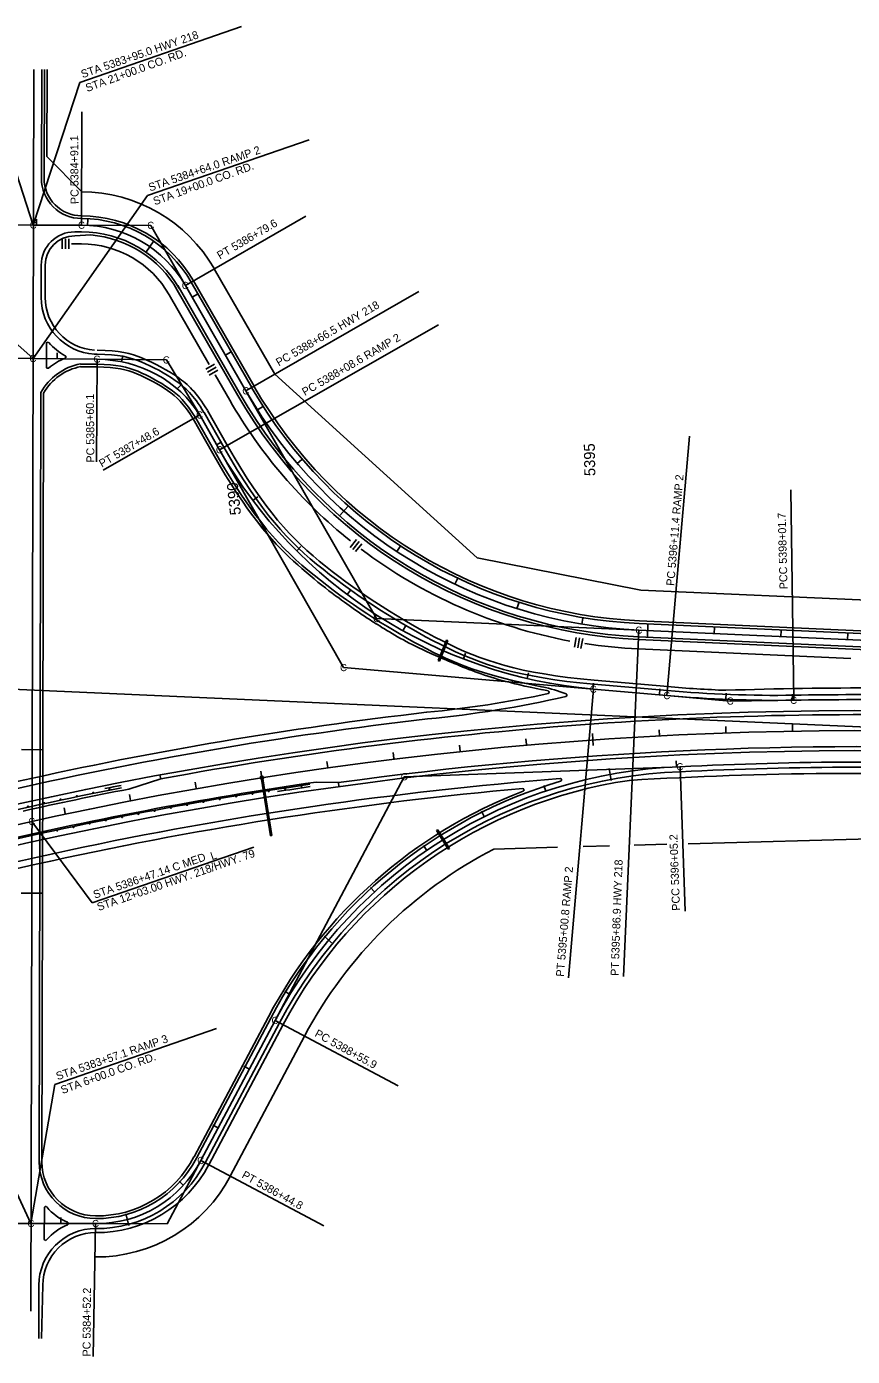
# Model space of a CAD drawing. Extents: x 192699 to 285914, y 194342 to 233219.
# Drawn here: x 282526 to 283763, y 220073 to 222066 of the extents above; entities that cross this region are included whole.
import ezdxf

# ---------------------------------------------------------------- set-up
doc = ezdxf.new("R2010")
doc.units = 0
for name, color, linetype in [('CENT LINE', 7, 'Continuous'), ('CONCRETE', 7, 'Continuous'), ('CURVE DATA', 7, 'Continuous'), ('CURVE LINE', 7, 'Continuous'), ('DRAINAGE', 7, 'Continuous'), ('GUARD RAILS', 7, 'Continuous'), ('R-W - CofA', 7, 'Continuous'), ('ROAD', 7, 'Continuous'), ('SHOULDER', 7, 'Continuous'), ('STATIONING1', 7, 'Continuous'), ('TEXT', 7, 'Continuous')]:
    doc.layers.add(name, color=color, linetype=linetype)

msp = doc.modelspace()

# ---------------------------------------------------------------- linework, layer by layer
at = {"layer": 'CENT LINE'}
for p, q in [((282531.8, 220140.9), (282536.2, 222002.1)), ((282442.4, 221769), (282535.6, 221768.8)), ((282535.6, 221768.8), (282607.9, 221768.6)), ((282763.6, 221678.2), (282854.2, 221520.3)), ((282453.4, 221569.7), (282631.3, 221567.7)), ((282785, 221484.1), (282814.7, 221432)), ((283443.5, 221161.5), (284035.7, 221135.1)), ((283375.2, 221073), (283485.4, 221063.5)), ((282898, 220576.6), (282786.7, 220366.6)), ((282404.9, 220272.5), (282532.1, 220272.2)), ((282532.1, 220272.2), (282629, 220272))]:
    msp.add_line(p, q, dxfattribs=at)
for centre, radius, start, end in [((282607.5, 221588.6), 180, 29.8667, 89.8681), ((283475.3, 221877), 716.2, 209.8667, 267.45), ((283650.1, 222966.2), 1909.9, 265.0516, 270.7606), ((283775, 215280.8), 5776.6, 87.38243, 90.99192), ((283775, 215280.8), 5730.1, 87.45001, 121.03334), ((283530.8, 220241), 716.2, 92.0659, 152.0654), ((283788.1, 215280.9), 5683, 87.5824, 92.8561), ((282630.7, 220447.8), 175.8, 269.4227, 332.4898)]:
    msp.add_arc(centre, radius, start, end, dxfattribs=at)
for centre, major_axis, ratio, start_param, end_param in [((282629.3, 221403.5), (178.6, 0), 0.919139, 0.512787, 1.560009), ((283440.8, 221780.5), (-718.5, 0), 0.988738, 0.51279, 1.479284)]:
    msp.add_ellipse(centre, major_axis=major_axis, ratio=ratio, start_param=start_param, end_param=end_param, dxfattribs=at)
at = {"layer": 'CONCRETE'}
for p, q in [((282726.5, 220938.6), (282725.4, 220944.5)), ((282726.5, 220938.6), (282678.6, 220923.4)), ((282993, 220933.1), (282959.8, 220933.9)), ((282993.8, 220927.1), (282993, 220933.1))]:
    msp.add_line(p, q, dxfattribs=at)
for radius, start, end in [(5711.6, 98.2059, 103.4241), (5748.1, 100.99633, 102.60615)]:
    msp.add_arc((283775, 215280.8), radius, start, end, dxfattribs=at)
at = {"layer": 'CURVE LINE'}
for p, q in [((282607.9, 221768.6), (282711.8, 221768.3)), ((282711.8, 221768.3), (282763.6, 221678.2)), ((282631.3, 221567.7), (282735.1, 221566.6)), ((282735.1, 221566.6), (282785, 221484.1)), ((282854.2, 221520.3), (283050.2, 221179)), ((282814.7, 221432), (283000.8, 221105.5)), ((283050.2, 221179), (283443.5, 221161.5)), ((283000.8, 221105.5), (283375.2, 221073)), ((282302.5, 221082.2), (284029.9, 221005.2)), ((283485.4, 221063.5), (283580.2, 221055.3)), ((283580.2, 221055.3), (283675.4, 221056.6)), ((283491, 220956.3), (283091.7, 220941.9)), ((283091.7, 220941.9), (282898, 220576.6)), ((282786.7, 220366.6), (282736.4, 220271.7)), ((282736.4, 220271.7), (282629, 220272))]:
    msp.add_line(p, q, dxfattribs=at)
at = {"layer": 'DRAINAGE'}
for p, q in [((283155, 221146.6), (283142.7, 221116)), ((283156.9, 221145.8), (283144.5, 221115.2)), ((283155, 221146.6), (283156.9, 221145.8)), ((283142.7, 221116), (283144.5, 221115.2)), ((282877.5, 220938.2), (282891, 220853.2)), ((282879.5, 220938.5), (282893, 220853.5)), ((283140.2, 220861), (283141.9, 220862)), ((283140.2, 220861), (283157.6, 220833)), ((283141.9, 220862), (283159.3, 220834)), ((283157.6, 220833), (283159.3, 220834))]:
    msp.add_line(p, q, dxfattribs=at)
msp.add_lwpolyline([(282876.5, 220938), (282880.5, 220938.6), (282879.8, 220942.6), (282875.9, 220942)], close=True, dxfattribs=at)
msp.add_lwpolyline([(282891, 220853.2), (282893, 220853.5)], dxfattribs=at)
at = {"layer": 'GUARD RAILS'}
for centre in [(282913, 220924.1), (282937.5, 220927.8), (282576.4, 220907.7), (282600.9, 220912.8), (282625.4, 220917.9), (282649.9, 220922.8), (282790.6, 220904), (282815, 220908.2), (282839.5, 220912.4), (282864, 220916.4), (282888.4, 220920.3), (282527.6, 220897), (282552, 220902.4), (282693, 220886.1), (282717.4, 220890.7), (282741.8, 220895.3), (282766.2, 220899.7), (282595.8, 220866.4), (282620, 220871.5), (282644.3, 220876.5), (282668.7, 220881.3), (282547.3, 220856), (282571.5, 220861.2)]:
    msp.add_circle(centre, 0.75, dxfattribs=at)
for radius, start, end in [(5752.1, 101.0959, 106.0764), (5709.6, 98.3062, 103.3237), (5755.7, 101.0959, 101.34483), (5706, 98.3062, 98.8041)]:
    msp.add_arc((283775, 215280.8), radius, start, end, dxfattribs=at)
at = {"layer": 'R-W - CofA'}
for p, q in [((282555.9, 221871.3), (282556.2, 222002.1)), ((282608.1, 221818.6), (282555.9, 221871.3)), ((282578.9, 221748.3), (282578.8, 221733.2)), ((282584, 221748.2), (282583.8, 221733.2)), ((282589, 221748.2), (282588.8, 221733.1)), ((282592.9, 221740.6), (282607.8, 221740.6)), ((282806.9, 221703.1), (282897.6, 221545.2)), ((282739.3, 221664.3), (282799.3, 221559.8)), ((282831.3, 221578.3), (282823.5, 221573.8)), ((282807.4, 221560.1), (282794.2, 221552.8)), ((282809.8, 221555.8), (282796.7, 221548.4)), ((282812.3, 221551.4), (282799.1, 221544)), ((282808.1, 221544.5), (282830, 221506.4)), ((283200.9, 221269.9), (282897.6, 221545.2)), ((282879.2, 221496.5), (282871.6, 221491.7)), ((282937.9, 221417.2), (282931.1, 221411.4)), ((283007.2, 221346.9), (282995.2, 221333.4)), ((283020, 221297.3), (283010.7, 221285.5)), ((283024, 221294.2), (283014.6, 221282.4)), ((283027.9, 221291.1), (283018.5, 221279.3)), ((283085.5, 221286.9), (283080.5, 221279.4)), ((283446.1, 221221.4), (283200.9, 221269.9)), ((283171.4, 221238.4), (283167.5, 221230.3)), ((283446.1, 221221.4), (284038.4, 221195.1)), ((283263.2, 221202.3), (283260.5, 221193.7)), ((283263.2, 221202.3), (283260.5, 221193.7)), ((283263.2, 221202.3), (283260.5, 221193.7)), ((283359.2, 221179.4), (283357.7, 221170.5)), ((283456.9, 221169.9), (283456.1, 221151.9)), ((283556.8, 221165.4), (283556.4, 221156.5)), ((283349.4, 221150.7), (283346.7, 221135.9)), ((283354.3, 221149.8), (283351.6, 221135)), ((283359.2, 221149), (283356.5, 221134.1)), ((283656.7, 221161), (283656.3, 221152)), ((283756.6, 221156.5), (283756.2, 221147.6)), ((283442.2, 221133.5), (283761.1, 221119.3)), ((283517.2, 220841.4), (284000.4, 220854.8)), ((283225.8, 220833.3), (283321.5, 220836)), ((283359.7, 220837), (283399.5, 220838.1)), ((283436.5, 220839.2), (283485, 220840.5)), ((282942.2, 220553.1), (282830.9, 220343.2))]:
    msp.add_line(p, q, dxfattribs=at)
for points in [[(282592.9, 221740.6), (282592.9, 221740.6)], [(282807.7, 221544.2), (282807.7, 221544.2)], [(283026.3, 221282.7), (283026.3, 221282.7)], [(283361.8, 221140.8), (283361.8, 221140.8)]]:
    msp.add_lwpolyline(points, dxfattribs=at)
for centre, radius, start, end in [((282607.5, 221588.6), 230, 29.8667, 89.8681), ((282607.5, 221588.6), 152, 29.8667, 89.8681), ((283475.3, 221877), 744.2, 209.8667, 231.4006), ((283475.3, 221877), 744.2, 232.9683, 259.5255), ((283475.3, 221877), 744.2, 261.2667, 267.45), ((283530.8, 220241), 666.2, 117.2457, 152.0654), ((282630.7, 220447.8), 225.8, 269.4227, 332.4898)]:
    msp.add_arc(centre, radius, start, end, dxfattribs=at)
at = {"layer": 'ROAD'}
for p, q in [((282547.8, 221838.8), (282548.2, 222002.1)), ((282607.6, 221778.6), (282607.9, 221778.6)), ((282597.6, 221758.6), (282607.9, 221758.6)), ((282547.4, 221659), (282547.5, 221708.8)), ((282772.2, 221683.2), (282862.9, 221525.3)), ((282752, 221678.2), (282845.6, 221515.3)), ((282555.1, 221556), (282555.2, 221591.1)), ((282627, 221575.3), (282631.3, 221575.2)), ((282606.2, 221560.5), (282631.2, 221560.2)), ((282544.4, 220364.7), (282547, 221517.8)), ((282791.5, 221487.8), (282821.2, 221435.7)), ((282778.5, 221480.4), (282808.2, 221428.3)), ((283443.9, 221171.5), (284036.1, 221145.1)), ((283443, 221151.5), (284035.3, 221125.1)), ((283375.8, 221080.5), (283486, 221071)), ((282517.8, 220982.4), (282549.8, 220982.3)), ((282549.3, 220767.3), (282549.8, 220982.3)), ((282517.3, 220767.4), (282549.3, 220767.3)), ((282891.4, 220580.1), (282780.1, 220370.1)), ((282904.6, 220573), (282793.3, 220363.1)), ((282552.1, 220248.8), (282552.2, 220295.5)), ((282543.7, 220099.7), (282543.9, 220179.7))]:
    msp.add_line(p, q, dxfattribs=at)
for centre, radius, start, end in [((282607.8, 221838.6), 60, 179.8667, 269.8702), ((282607.5, 221588.6), 190, 29.8667, 89.8681), ((282597.5, 221708.6), 50, 89.8702, 179.8667), ((282607.5, 221588.6), 170, 29.8667, 89.8681), ((282632.4, 221660.1), 85, 179.8667, 266.3998), ((282557.2, 221591.1), 2, 42.5431, 179.8667), ((282622.9, 221648.2), 85, 220.9203, 242.3594), ((282613.8, 221489.9), 85, 111.0237, 130.6469), ((282582.5, 221571.1), 2, 292.5068, 60.7366), ((282621.5, 221476.9), 85, 100.3923, 151.2275), ((282557.1, 221556), 2, 179.8667, 309.1637), ((283475.3, 221877), 706.2, 209.8667, 267.45), ((283475.3, 221877), 726.2, 209.8667, 267.45), ((283257.6, 220873.2), 207.4, 68.3245, 78.5418), ((283333.4, 221064.1), 2.01, 284.0686, 65.5581), ((283650.1, 222966.2), 1902.4, 265.0516, 270.7606), ((283775, 215280.8), 5784.1, 87.45001, 90.98754), ((282977, 222603.4), 1582, 275.4138, 283.036), ((283775, 215280.8), 5760.1, 87.45001, 121.03334), ((283802.9, 215159.4), 5907.9, 96.57627, 109.29763), ((283775, 215280.8), 5700.1, 87.45, 121.0333), ((283530.8, 220241), 708.7, 92.0659, 152.0654), ((283788.1, 215280.7), 5675.6, 87.5826, 92.857), ((283775, 215280.8), 5676.1, 94.5449, 109.6075), ((283530.8, 220241), 723.7, 106.4426, 152.0654), ((283325.4, 220937.1), 2, 286.4426, 94.5449), ((282630.7, 220447.8), 168.3, 269.4227, 332.4898), ((282629.4, 220364.5), 85, 179.8667, 269.8667), ((282630.7, 220447.8), 183.3, 269.4227, 332.4898), ((282554.2, 220295.5), 2, 42.5346, 179.8667), ((282620.3, 220352.1), 85, 220.5245, 246.952), ((282619.9, 220191.9), 85, 112.7814, 139.2089), ((282586.2, 220272.1), 2, 294.7915, 64.9419), ((282628.9, 220179.5), 85, 89.8667, 179.8667), ((282554.1, 220248.8), 2, 179.8667, 317.1988)]:
    msp.add_arc(centre, radius, start, end, dxfattribs=at)
for points in [[(282791.4, 221488), (282775.3, 221514.3), (282752, 221536.2), (282695.8, 221566.7), (282663.9, 221574.9), (282631.3, 221575.2)], [(282778.6, 221480.2), (282763.9, 221504.1), (282742.6, 221524.2), (282690.9, 221552.3), (282661.3, 221559.9), (282631.2, 221560.2)], [(282808.2, 221428.3), (282865.9, 221327), (282947.5, 221241.1), (283123.6, 221128.3), (283209.7, 221093.9), (283299.7, 221076.3)], [(282821.2, 221435.7), (282877.7, 221336.5), (282957.6, 221252.4), (283150.9, 221128.7), (283261.2, 221090.9), (283375.8, 221080.5)]]:
    msp.add_open_spline(points, degree=3, dxfattribs=at)
at = {"layer": 'SHOULDER'}
for p, q in [((282551.8, 221838.7), (282552.2, 222002.1)), ((282607.7, 221782.6), (282607.9, 221782.6)), ((282597.6, 221752.6), (282621.6, 221754)), ((282553.4, 221659), (282553.5, 221708.7)), ((282775.7, 221685.2), (282866.4, 221527.3)), ((282751.4, 221671.3), (282842.1, 221513.3)), ((282606.2, 221556.5), (282631.1, 221556.2)), ((282549.8, 220982.3), (282551, 221516.8)), ((282796.7, 221490.8), (282826.4, 221438.7)), ((282775, 221478.4), (282804.7, 221426.3)), ((283444.1, 221175.5), (284036.3, 221149.1)), ((283442.8, 221147.5), (284035.1, 221121.1)), ((283376.3, 221086.5), (283486.5, 221077)), ((282548.4, 220364.7), (282549.3, 220767.3)), ((282887.9, 220581.9), (282776.5, 220372)), ((282909.9, 220570.2), (282798.6, 220360.3)), ((282547.7, 220099.7), (282549.9, 220179.7))]:
    msp.add_line(p, q, dxfattribs=at)
for centre, radius, start, end in [((282607.8, 221838.6), 56, 179.8667, 269.8702), ((282607.5, 221588.6), 194, 29.8667, 89.8681), ((282597.5, 221708.6), 44, 89.8702, 179.8667), ((282607.5, 221588.6), 166, 29.8667, 85.1342), ((282632.4, 221660.1), 79, 179.8667, 266.3998), ((282621.5, 221476.9), 81, 100.3923, 150.5134), ((283475.3, 221877), 702.2, 209.8667, 267.45), ((283475.3, 221877), 730.2, 209.8667, 267.45), ((282977, 222603.4), 1572, 275.4138, 282.1329), ((283257.6, 220873.2), 203.4, 75.8, 78.5418), ((283307, 221068.4), 2, 282.1329, 75.8), ((283650.1, 222966.2), 1896.4, 265.0516, 267.6948), ((283775, 215280.8), 5794.1, 87.45001, 91.98963), ((283802.9, 215159.4), 5917.9, 96.57627, 108.59585), ((283775, 215280.8), 5754.1, 87.45001, 100.49846), ((283775, 215280.8), 5706.1, 87.45, 97.8773), ((283775, 215280.8), 5666.1, 87.45, 93.5008), ((283530.8, 220241), 702.7, 98.3276, 152.0654), ((283775, 215280.8), 5666.1, 95.1221, 109.6075), ((283530.8, 220241), 727.7, 110.9973, 152.0654), ((283269.3, 220922.3), 2, 290.9973, 95.1221), ((282630.7, 220447.8), 164.3, 269.4227, 332.4898), ((282629.4, 220364.5), 81, 179.8667, 269.8667), ((282630.7, 220447.8), 189.3, 269.4227, 332.4898), ((282628.9, 220179.5), 79, 89.8667, 179.8667)]:
    msp.add_arc(centre, radius, start, end, dxfattribs=at)
for points in [[(282796.5, 221491.2), (282779.8, 221518.4), (282755.7, 221540.9), (282697.8, 221572.5), (282664.9, 221580.9), (282631.4, 221581.2)], [(282775.2, 221478.1), (282760.9, 221501.4), (282740.1, 221521), (282689.5, 221548.5), (282660.6, 221555.9), (282631.1, 221556.2)], [(282804.7, 221426.3), (282856.5, 221335.4), (282927.4, 221256.8), (283023.3, 221188.2), (283034.1, 221180.8), (283056.3, 221166.7), (283090, 221146.4), (283125.2, 221129), (283197.3, 221098), (283247.5, 221082.4), (283298.9, 221072.3)], [(282826.4, 221438.6), (282882.4, 221340.4), (282961.7, 221256.9), (283153.3, 221134.2), (283262.7, 221096.8), (283376.4, 221086.5)]]:
    msp.add_open_spline(points, degree=3, dxfattribs=at)
at = {"layer": 'STATIONING1'}
for p, q in [((282605.3, 221982.6), (282847.7, 222066.3)), ((282535.6, 221768.8), (282605.3, 221982.6)), ((282535.6, 221768.8), (282471.8, 221964.9)), ((282607.9, 221768.6), (282608.3, 221938.5)), ((282706.5, 221812.9), (282949, 221896.5)), ((282535.2, 221568.8), (282271.8, 221802.2)), ((282535.2, 221568.8), (282706.5, 221812.9)), ((282763.6, 221678.2), (282944.1, 221781.9)), ((282540.6, 221777.8), (282540.6, 221768.8)), ((282617.3, 221777.3), (282616.8, 221768.3)), ((282715.4, 221743.8), (282705.1, 221729)), ((282781.5, 221665), (282773.7, 221660.5)), ((282854.2, 221520.3), (283113.4, 221669.1)), ((282814.7, 221432), (283143.1, 221619.1)), ((282571.3, 221577.4), (282571.2, 221568.4)), ((282631.3, 221567.7), (282630.4, 221413.9)), ((282669.8, 221572.7), (282667.7, 221563.9)), ((282757.9, 221529.7), (282751.4, 221523.4)), ((282785, 221484.1), (282640.3, 221401.6)), ((282818.3, 221443.9), (282810.4, 221439.4)), ((283485.4, 221063.5), (283519, 221452.3)), ((283675.4, 221056.6), (283671.2, 221371.7)), ((282871.9, 221361.3), (282864.7, 221355.9)), ((282936.8, 221286.9), (282930.4, 221280.5)), ((283011.3, 221222.2), (283005.9, 221215)), ((283094.1, 221168.5), (283089.7, 221160.7)), ((283443.5, 221161.5), (283420.3, 220642.2)), ((283183.5, 221126.8), (283180.3, 221118.4)), ((283277.8, 221097.8), (283275.8, 221089.1)), ((283375.2, 221073), (283337.7, 220640.5)), ((283375.2, 221082.1), (283374.4, 221073.1)), ((283474.7, 221073.5), (283474, 221064.5)), ((283574.1, 221066.9), (283573.8, 221057.9)), ((283673.6, 221065.5), (283673.7, 221056.5)), ((283373.8, 221006.7), (283374.8, 220988.7)), ((283473.5, 221012), (283474, 221003)), ((283573.7, 221017.2), (283573.9, 221008.2)), ((283673.7, 221019.9), (283673.7, 221010.9)), ((283174.4, 220989.2), (283175.2, 220980.3)), ((283274, 220998.8), (283274.7, 220989.9)), ((282975.8, 220964.8), (282976.9, 220955.9)), ((283075, 220977.9), (283075.9, 220969)), ((283499.4, 220965.6), (283499.8, 220956.6)), ((282876.8, 220950), (282879.3, 220932.2)), ((283398.9, 220954.2), (283402, 220936.4)), ((283505, 220956.8), (283512.8, 220740.3)), ((282778.1, 220933.5), (282779.5, 220924.6)), ((283300.9, 220928.9), (283303.7, 220920.3)), ((282679.7, 220915.3), (282681.3, 220906.4)), ((282581.6, 220895.3), (282583.3, 220886.5)), ((283207.5, 220890.2), (283211.4, 220882.1)), ((282533.5, 220874.8), (282623.7, 220752.8)), ((282623.7, 220752.8), (282866.1, 220836.4)), ((283120.3, 220838.9), (283125.3, 220831.4)), ((283041, 220775.9), (283047.1, 220769.2)), ((282971.4, 220702.6), (282985.2, 220691)), ((282912.6, 220620.2), (282920.2, 220615.5)), ((282898, 220576.6), (283082.6, 220478.7)), ((282568, 220480.7), (282810.4, 220564.3)), ((282851.4, 220508), (282859.4, 220503.7)), ((282532.1, 220272.2), (282429.5, 220490.5)), ((282532.1, 220272.2), (282568, 220480.7)), ((282804.5, 220419.6), (282812.6, 220415.4)), ((282786.7, 220366.6), (282971.2, 220268.8)), ((282754, 220335.4), (282760.6, 220329.3)), ((282674.1, 220286.7), (282678.7, 220269.2)), ((282576.8, 220281.1), (282576.8, 220272.1)), ((282629, 220272), (282625.4, 220072.9))]:
    msp.add_line(p, q, dxfattribs=at)

# ---------------------------------------------------------------- texts
at = {"layer": 'CURVE DATA'}
for p in [(282530.5, 221763.1), (282602.8, 221762.9), (282706.7, 221762.6), (282758.4, 221672.5), (282530, 221563.1), (282626.1, 221562), (282730, 221560.9), (282849.1, 221514.6), (282779.9, 221478.4), (282809.6, 221426.3), (283045.1, 221173.3), (283438.3, 221155.8), (282995.6, 221099.8), (283370, 221067.3), (283480.2, 221057.8), (283575.1, 221049.6), (283670.3, 221050.8), (283086.6, 220936.2), (283499.8, 220951.1), (282528.4, 220869.1), (282892.9, 220570.8), (282781.6, 220360.9), (282527, 220266.5), (282623.8, 220266.3)]:
    msp.add_text('C', height=10.8, rotation=3.0667, dxfattribs=at).set_placement(p)
at = {"layer": 'STATIONING1'}
for s, rotation, p in [('5395', 91.0333, (283378.1, 221392.6)), ('5390', 96.0333, (282847, 221334.8))]:
    msp.add_text(s, height=16.5, rotation=rotation, dxfattribs=at).set_placement(p)
at = {"layer": 'TEXT'}
for s, rotation, p in [('STA 5383+95.0 HWY 218', 19.0333, (282609.4, 221988.8)), ('STA 21+00.0 CO. RD.', 20.0046, (282616.5, 221968.1)), ('PC 5384+91.1', 90.3975, (282603.5, 221800.3)), ('STA 5384+64.0 RAMP 2', 19.0333, (282710.6, 221819)), ('STA 19+00.0 CO. RD.', 20.0046, (282717.8, 221798.3)), ('PT 5386+79.6', 30.2998, (282815.3, 221717)), ('PC 5388+66.5 HWY 218', 30.2998, (282903.6, 221556.7)), ('PC 5388+08.6 RAMP 2', 30.2998, (282942.7, 221512.4)), ('PC 5385+60.1', 90.3975, (282627.2, 221412.8)), ('PT 5387+48.6', 30.2998, (282638.4, 221405)), ('PC 5396+11.4 RAMP 2', 85.1472, (283496.2, 221227.6)), ('PCC 5398+01.7', 91.366, (283666.2, 221223)), ('PCC 5396+05.2', 92.0543, (283505.1, 220741.2)), ('STA 5386+47.14 C MED', 19.0333, (282627.8, 220758.9)), ('STA 12+03.00 HWY. 218/HWY. 79', 19.1431, (282633.5, 220740.5)), ('L', 19.0333, (282803.5, 220816.6)), ('PT 5395+00.8 RAMP 2', 85.2306, (283330.9, 220641.7)), ('PT 5395+86.9 HWY 218', 87.9934, (283412.9, 220643.2)), ('STA 5383+57.1 RAMP 3', 19.0333, (282572.1, 220486.8)), ('PC 5388+55.9', 331.0722, (282956.3, 220553.3)), ('STA 6+00.0 CO. RD.', 20.0046, (282579.3, 220466.1)), ('PT 5386+44.8', 331.0722, (282847, 220341.3)), ('PC 5384+52.2', 89.6993, (282621.4, 220072.8))]:
    msp.add_text(s, height=12, rotation=rotation, dxfattribs=at).set_placement(p)

doc.saveas('drawing.dxf')
